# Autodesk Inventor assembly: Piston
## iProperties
Created: 2002-08
Part Number: Piston
Document SubType Name: Assembly
Designer: t_munrn
Control State: 0
Master: False
Checked Out: False
Shininess: 64.0
Length Units: 11269
Angle Units: 11279
Time Units: 11290
Mass Units: 11283
Length Display Precision: 3
Angle Display Precision: 2
Density: 0.0
Volumn: 0.0
Area: 0.0
PropertySet Name: Model Information
Author: t_munrn
